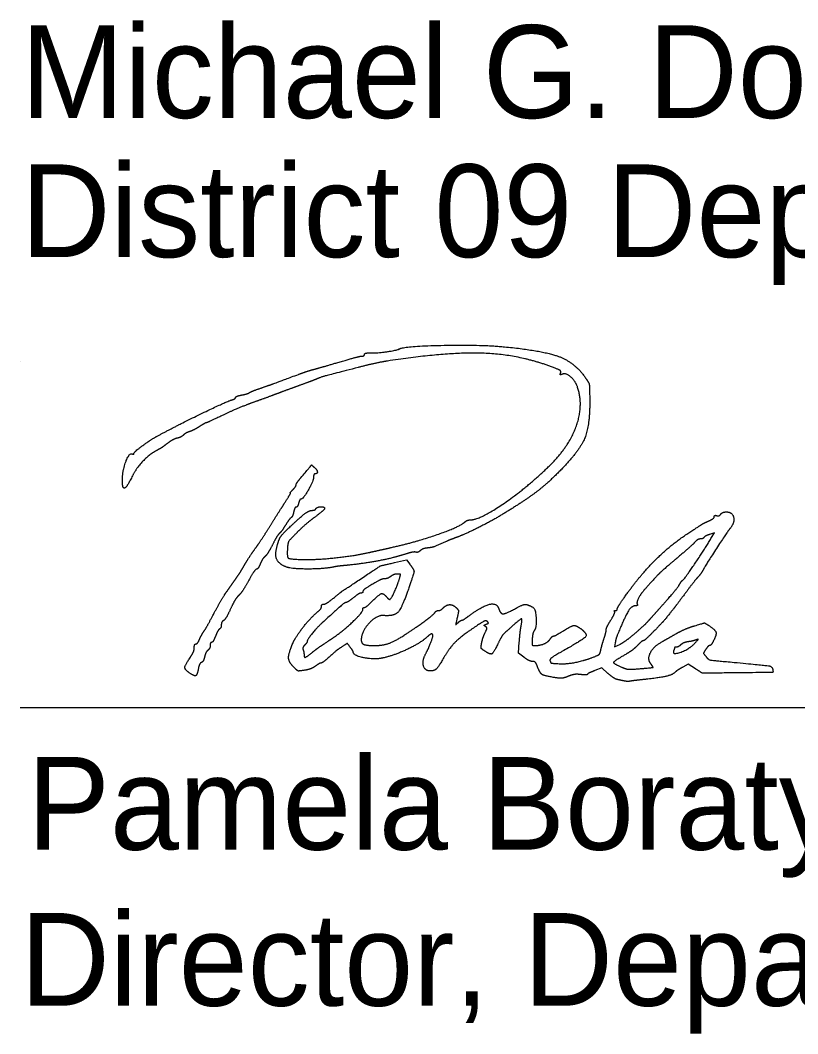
# Model space of a CAD drawing. Extents: x 0 to 34, y 0 to 22.
# Drawn here: x 24.528 to 25.701, y 7.305 to 8.834 of the extents above; entities that cross this region are included whole.
import ezdxf

# ---------------------------------------------------------------- set-up
doc = ezdxf.new("R2010")
doc.units = 0
for name, color, linetype in [('Default', 7, 'Continuous'), ('SH_Data', 7, 'Continuous'), ('SH_Text', 7, 'Continuous')]:
    doc.layers.add(name, color=color, linetype=linetype)

msp = doc.modelspace()

# ---------------------------------------------------------------- linework, layer by layer
at = {"layer": 'Default'}
for points in [[(25.5703, 8.0517), (25.5756, 8.0607), (25.5683, 8.0581)], [(25.0929, 8.0156), (25.1109, 8.0196), (25.1156, 8.0134)], [(25.2879, 7.8728), (25.2796, 7.8791), (25.281, 7.8962)], [(25.4259, 7.8947), (25.4249, 7.8883), (25.4335, 7.8927)], [(25.5467, 7.8554), (25.5361, 7.8622), (25.5277, 7.8577)], [(25.4148, 7.8484), (25.4057, 7.8567), (25.3951, 7.8526)]]:
    msp.add_lwpolyline(points, dxfattribs=at)
for points in [[(25.0563, 8.3319), (25.0659, 8.3317), (25.0969, 8.336), (25.1003, 8.3381)], [(25.1003, 8.3381), (25.1071, 8.3423), (25.2241, 8.3446), (25.2585, 8.3412)], [(25.2585, 8.3412), (25.3178, 8.3354), (25.3653, 8.3171), (25.3811, 8.2941)], [(25.0106, 8.3186), (25.0267, 8.3233), (25.0415, 8.3272), (25.0436, 8.3272)], [(25.0821, 8.3197), (25.0729, 8.3183), (25.0529, 8.3139), (25.0377, 8.31)], [(25.0436, 8.3272), (25.0457, 8.3272), (25.0473, 8.3283), (25.0473, 8.3297)], [(25.0473, 8.3297), (25.0473, 8.3311), (25.0514, 8.3321), (25.0563, 8.3319)], [(25.331, 8.3105), (25.2805, 8.3295), (25.1725, 8.3335), (25.0821, 8.3197)], [(24.9477, 8.2996), (24.9557, 8.3025), (24.9665, 8.3061), (24.9717, 8.3074)], [(24.9717, 8.3074), (24.977, 8.3088), (24.9945, 8.3138), (25.0106, 8.3186)], [(25.0377, 8.31), (24.9867, 8.2968), (24.9825, 8.2956), (24.9717, 8.2912)], [(25.3434, 8.3019), (25.3443, 8.3044), (25.3409, 8.3068), (25.331, 8.3105)], [(24.8913, 8.279), (24.9061, 8.2841), (24.9125, 8.2864), (24.9477, 8.2996)], [(24.9717, 8.2912), (24.9691, 8.2901), (24.9588, 8.2863), (24.9489, 8.2827)], [(25.3458, 8.2998), (25.3432, 8.2988), (25.3424, 8.2994), (25.3434, 8.3019)], [(25.3691, 8.2799), (25.3659, 8.2896), (25.3514, 8.302), (25.3458, 8.2998)], [(25.3811, 8.2941), (25.3861, 8.2868), (25.387, 8.2825), (25.3873, 8.2646)], [(24.8733, 8.2718), (24.8747, 8.2728), (24.8828, 8.276), (24.8913, 8.279)], [(24.9489, 8.2827), (24.939, 8.2791), (24.9239, 8.2736), (24.9153, 8.2703)], [(25.3236, 8.1587), (25.3546, 8.1881), (25.3784, 8.2516), (25.3691, 8.2799)], [(24.7353, 8.2068), (24.7656, 8.2231), (24.8392, 8.2587), (24.8475, 8.2612)], [(24.8475, 8.2612), (24.8505, 8.262), (24.8529, 8.2636), (24.8529, 8.2647)], [(24.8529, 8.2647), (24.8529, 8.2658), (24.857, 8.2674), (24.8619, 8.2684)], [(24.8619, 8.2684), (24.8669, 8.2693), (24.872, 8.2708), (24.8733, 8.2718)], [(24.9153, 8.2703), (24.9068, 8.2671), (24.8906, 8.2612), (24.8793, 8.2572)], [(25.3873, 8.2646), (25.3881, 8.2238), (25.372, 8.1841), (25.3426, 8.1542)], [(24.8793, 8.2572), (24.8681, 8.2532), (24.8478, 8.2447), (24.8341, 8.2382)], [(24.8341, 8.2382), (24.8205, 8.2317), (24.8088, 8.2264), (24.8083, 8.2264)], [(24.7835, 8.2132), (24.7802, 8.2122), (24.7761, 8.2099), (24.7743, 8.2081)], [(24.7983, 8.2208), (24.7934, 8.2177), (24.7867, 8.2143), (24.7835, 8.2132)], [(24.8083, 8.2264), (24.8077, 8.2264), (24.8032, 8.2239), (24.7983, 8.2208)], [(24.6993, 8.1802), (24.6993, 8.1823), (24.7247, 8.2011), (24.7353, 8.2068)], [(24.7646, 8.2033), (24.761, 8.2024), (24.7544, 8.1988), (24.7497, 8.1952)], [(24.7743, 8.2081), (24.7725, 8.2063), (24.7681, 8.2041), (24.7646, 8.2033)], [(24.7339, 8.1848), (24.7234, 8.1795), (24.7035, 8.1587), (24.6973, 8.1465)], [(24.7497, 8.1952), (24.7451, 8.1916), (24.738, 8.1869), (24.7339, 8.1848)], [(24.6822, 8.1423), (24.6823, 8.1555), (24.6929, 8.1821), (24.697, 8.1795)], [(24.697, 8.1795), (24.6983, 8.1788), (24.6993, 8.1791), (24.6993, 8.1802)], [(24.9495, 8.1413), (24.9681, 8.1634), (24.9674, 8.1628), (24.9715, 8.1594)], [(24.9715, 8.1594), (24.9758, 8.1559), (24.9767, 8.1496), (24.9729, 8.1496)], [(25.2069, 8.08), (25.221, 8.08), (25.2891, 8.1259), (25.3236, 8.1587)], [(25.3426, 8.1542), (25.324, 8.1354), (25.2916, 8.1104), (25.2611, 8.0916)], [(24.6835, 8.1286), (24.6827, 8.1294), (24.6821, 8.1356), (24.6822, 8.1423)], [(24.6973, 8.1465), (24.6907, 8.1336), (24.6854, 8.1268), (24.6835, 8.1286)], [(24.9441, 8.1326), (24.9441, 8.1338), (24.9466, 8.1377), (24.9495, 8.1413)], [(24.9705, 8.1445), (24.9705, 8.139), (24.9546, 8.1112), (24.9514, 8.1112)], [(24.9729, 8.1496), (24.9716, 8.1496), (24.9705, 8.1473), (24.9705, 8.1445)], [(24.9356, 8.1208), (24.935, 8.1208), (24.9367, 8.123), (24.9393, 8.1256)], [(24.9393, 8.1256), (24.942, 8.1283), (24.9441, 8.1314), (24.9441, 8.1326)], [(24.9266, 8.1051), (24.9321, 8.1138), (24.9362, 8.1208), (24.9356, 8.1208)], [(24.9514, 8.1112), (24.9503, 8.1112), (24.9488, 8.1085), (24.948, 8.1052)], [(24.9045, 8.0701), (24.9111, 8.0808), (24.9211, 8.0965), (24.9266, 8.1051)], [(24.9357, 8.0703), (24.9514, 8.0849), (24.9642, 8.0944), (24.9681, 8.0944)], [(24.9405, 8.092), (24.9397, 8.0881), (24.9379, 8.0842), (24.9367, 8.0834)], [(24.9443, 8.0992), (24.9431, 8.0992), (24.9414, 8.096), (24.9405, 8.092)], [(24.948, 8.1052), (24.9471, 8.1019), (24.9455, 8.0992), (24.9443, 8.0992)], [(24.9681, 8.0944), (24.9706, 8.0944), (24.9733, 8.0955), (24.9741, 8.0968)], [(24.9873, 8.0972), (24.9873, 8.0961), (24.9806, 8.0902), (24.9723, 8.0841)], [(24.9741, 8.0968), (24.9759, 8.0997), (24.9873, 8.1), (24.9873, 8.0972)], [(25.2611, 8.0916), (25.2419, 8.0798), (25.2006, 8.0588), (25.1865, 8.0537)], [(25.5851, 8.0886), (25.5866, 8.0905), (25.5903, 8.092), (25.5933, 8.092)], [(25.5933, 8.092), (25.6027, 8.092), (25.6064, 8.076), (25.599, 8.067)], [(24.9367, 8.0834), (24.9354, 8.0827), (24.9316, 8.0775), (24.9282, 8.072)], [(24.9723, 8.0841), (24.9641, 8.078), (24.9516, 8.0671), (24.9446, 8.0599)], [(25.0869, 8.0381), (25.1239, 8.0463), (25.1901, 8.0692), (25.1987, 8.0767)], [(25.1987, 8.0767), (25.2008, 8.0785), (25.2045, 8.08), (25.2069, 8.08)], [(25.5386, 8.0616), (25.5575, 8.0739), (25.5594, 8.075), (25.5675, 8.0787)], [(25.5675, 8.0787), (25.5718, 8.0806), (25.5753, 8.0834), (25.5753, 8.0849)], [(25.5753, 8.0849), (25.5753, 8.0865), (25.5769, 8.0871), (25.5788, 8.0864)], [(25.5788, 8.0864), (25.5806, 8.0857), (25.5835, 8.0867), (25.5851, 8.0886)], [(24.8828, 8.0372), (24.8882, 8.0447), (24.8979, 8.0595), (24.9045, 8.0701)], [(24.9144, 8.0356), (24.9172, 8.0487), (24.9233, 8.0587), (24.9357, 8.0703)], [(24.9282, 8.072), (24.9248, 8.0665), (24.9207, 8.0609), (24.919, 8.0596)], [(24.9446, 8.0599), (24.9338, 8.049), (24.9317, 8.0453), (24.9311, 8.0371)], [(25.4439, 7.9691), (25.4662, 7.9999), (25.5112, 8.0439), (25.5386, 8.0616)], [(25.599, 8.067), (25.5949, 8.062), (25.562, 8.0115), (25.5589, 8.0053)], [(24.919, 8.0596), (24.9173, 8.0582), (24.9127, 8.0506), (24.9087, 8.0426)], [(25.1709, 8.0475), (25.1538, 8.04), (25.149, 8.0383), (25.1423, 8.0376)], [(25.1865, 8.0537), (25.1819, 8.052), (25.1749, 8.0492), (25.1709, 8.0475)], [(25.5454, 8.0458), (25.5427, 8.0428), (25.5303, 8.0318), (25.5177, 8.0212)], [(25.5275, 7.9888), (25.5303, 7.9908), (25.5585, 8.0323), (25.5703, 8.0517)], [(25.5543, 8.0512), (25.5521, 8.0512), (25.5481, 8.0488), (25.5454, 8.0458)], [(25.5596, 8.0534), (25.5589, 8.0522), (25.5565, 8.0512), (25.5543, 8.0512)], [(25.5683, 8.0581), (25.5642, 8.0567), (25.5603, 8.0546), (25.5596, 8.0534)], [(24.8661, 8.0116), (24.8699, 8.0182), (24.8774, 8.0297), (24.8828, 8.0372)], [(24.9087, 8.0426), (24.9046, 8.0347), (24.8996, 8.0267), (24.8974, 8.0249)], [(24.9297, 8.0088), (24.9193, 8.0127), (24.9122, 8.0251), (24.9144, 8.0356)], [(24.9311, 8.0371), (24.9303, 8.0236), (24.9343, 8.0208), (24.9549, 8.0202)], [(24.9549, 8.0202), (24.9742, 8.0197), (25.032, 8.0258), (25.0533, 8.0306)], [(25.0533, 8.0306), (25.0613, 8.0324), (25.0764, 8.0357), (25.0869, 8.0381)], [(25.1247, 8.0313), (25.1231, 8.0319), (25.115, 8.0303), (25.1067, 8.0276)], [(25.1315, 8.0335), (25.1294, 8.0317), (25.1264, 8.0307), (25.1247, 8.0313)], [(25.1423, 8.0376), (25.1385, 8.0372), (25.1336, 8.0353), (25.1315, 8.0335)], [(24.8974, 8.0249), (24.8952, 8.0231), (24.892, 8.018), (24.8901, 8.0136)], [(25.1067, 8.0276), (25.0903, 8.0223), (25.0452, 8.0138), (25.0214, 8.0115)], [(25.0389, 7.9892), (25.0706, 8.0102), (25.072, 8.0109), (25.0929, 8.0156)], [(25.5177, 8.0212), (25.4981, 8.0047), (25.4864, 7.9933), (25.4697, 7.9744)], [(24.853, 7.991), (24.8564, 7.9957), (24.8622, 8.005), (24.8661, 8.0116)], [(24.8844, 8.0056), (24.8831, 8.0056), (24.8777, 7.9977), (24.8724, 7.9881)], [(24.8901, 8.0136), (24.8883, 8.0092), (24.8857, 8.0056), (24.8844, 8.0056)], [(25.001, 8.0089), (24.9873, 8.0059), (24.9378, 8.0058), (24.9297, 8.0088)], [(25.0214, 8.0115), (25.013, 8.0107), (25.0039, 8.0096), (25.001, 8.0089)], [(25.1156, 8.0134), (25.1222, 8.0047), (25.1221, 7.9998), (25.1143, 7.9773)], [(25.5589, 8.0053), (25.5571, 8.0019), (25.5532, 7.9964), (25.5502, 7.9932)], [(24.8395, 7.9718), (24.8436, 7.9776), (24.8497, 7.9862), (24.853, 7.991)], [(24.8724, 7.9881), (24.8671, 7.9784), (24.8604, 7.9684), (24.8575, 7.9659)], [(24.9997, 7.9612), (25.0134, 7.9723), (25.0115, 7.9709), (25.0389, 7.9892)], [(25.0686, 7.9881), (25.0542, 7.9801), (25.0449, 7.9738), (25.0449, 7.9718)], [(25.0784, 7.9912), (25.0761, 7.9912), (25.0717, 7.9898), (25.0686, 7.9881)], [(25.0871, 7.9947), (25.0845, 7.9928), (25.0806, 7.9912), (25.0784, 7.9912)], [(25.0856, 7.96), (25.0874, 7.96), (25.0971, 7.9811), (25.1003, 7.9918)], [(25.097, 7.9983), (25.0941, 7.9983), (25.0896, 7.9967), (25.0871, 7.9947)], [(25.1003, 7.9918), (25.102, 7.9976), (25.1016, 7.9984), (25.097, 7.9983)], [(25.4922, 7.9459), (25.5076, 7.963), (25.5211, 7.9793), (25.5235, 7.9837)], [(25.5235, 7.9837), (25.5247, 7.9858), (25.5265, 7.9882), (25.5275, 7.9888)], [(25.5502, 7.9932), (25.5473, 7.99), (25.5384, 7.9786), (25.5305, 7.968)], [(24.8206, 7.9396), (24.8269, 7.9515), (24.8354, 7.966), (24.8395, 7.9718)], [(25.0423, 7.9696), (25.0408, 7.9696), (25.0355, 7.9664), (25.0305, 7.9624)], [(25.0449, 7.9718), (25.0449, 7.9706), (25.0437, 7.9696), (25.0423, 7.9696)], [(25.0593, 7.9576), (25.0695, 7.9677), (25.076, 7.9696), (25.0809, 7.9636)], [(25.1143, 7.9773), (25.1041, 7.9474), (25.0921, 7.9343), (25.0761, 7.9356)], [(25.4289, 7.9458), (25.4289, 7.9472), (25.4357, 7.9577), (25.4439, 7.9691)], [(25.4697, 7.9744), (25.4639, 7.9678), (25.4576, 7.955), (25.4591, 7.9526)], [(25.5305, 7.968), (25.5226, 7.9573), (25.5149, 7.9471), (25.5134, 7.9453)], [(24.8575, 7.9659), (24.8547, 7.9633), (24.8492, 7.9542), (24.8452, 7.9456)], [(24.9825, 7.9494), (24.9825, 7.9513), (24.9841, 7.9528), (24.9859, 7.9528)], [(25.0194, 7.9552), (25.0175, 7.9552), (25.009, 7.9479), (24.9837, 7.9247)], [(24.9859, 7.9528), (24.9878, 7.9528), (24.994, 7.9566), (24.9997, 7.9612)], [(25.0305, 7.9624), (25.0255, 7.9585), (25.0205, 7.9552), (25.0194, 7.9552)], [(25.0473, 7.948), (25.0487, 7.948), (25.0541, 7.9523), (25.0593, 7.9576)], [(25.0809, 7.9636), (25.0826, 7.9616), (25.0847, 7.96), (25.0856, 7.96)], [(25.2041, 7.9345), (25.2244, 7.9497), (25.2471, 7.9553), (25.2501, 7.9459)], [(24.8051, 7.912), (24.8074, 7.9153), (24.8143, 7.9277), (24.8206, 7.9396)], [(24.8452, 7.9456), (24.8413, 7.937), (24.8366, 7.9291), (24.8347, 7.9281)], [(24.9391, 7.8933), (24.9435, 7.9038), (24.9668, 7.9332), (24.9771, 7.9416)], [(24.9771, 7.9416), (24.9801, 7.944), (24.9825, 7.9475), (24.9825, 7.9494)], [(24.9989, 7.9014), (25.0145, 7.9118), (25.0449, 7.9406), (25.0449, 7.9449)], [(25.0449, 7.9449), (25.0449, 7.9466), (25.046, 7.948), (25.0473, 7.948)], [(25.1109, 7.9083), (25.1295, 7.9207), (25.1519, 7.9374), (25.1537, 7.9401)], [(25.1537, 7.9401), (25.1547, 7.9418), (25.1571, 7.9432), (25.1589, 7.9432)], [(25.1589, 7.9432), (25.1607, 7.9432), (25.164, 7.945), (25.1661, 7.9471)], [(25.1661, 7.9471), (25.1711, 7.9521), (25.1811, 7.9521), (25.186, 7.9472)], [(25.186, 7.9472), (25.1892, 7.944), (25.1894, 7.9416), (25.1873, 7.9324)], [(25.2501, 7.9459), (25.2525, 7.9383), (25.2606, 7.9382), (25.2738, 7.9455)], [(25.2738, 7.9455), (25.2858, 7.9521), (25.293, 7.9528), (25.3013, 7.9482)], [(25.3013, 7.9482), (25.3056, 7.9458), (25.3073, 7.9178), (25.3034, 7.9126)], [(25.4192, 7.9289), (25.423, 7.9352), (25.4256, 7.941), (25.4248, 7.9418)], [(25.4248, 7.9418), (25.424, 7.9426), (25.4246, 7.9432), (25.4261, 7.9432)], [(25.4261, 7.9432), (25.4277, 7.9432), (25.4289, 7.9444), (25.4289, 7.9458)], [(25.4568, 7.9504), (25.4505, 7.9504), (25.4409, 7.9352), (25.4289, 7.906)], [(25.4591, 7.9526), (25.4598, 7.9514), (25.4588, 7.9504), (25.4568, 7.9504)], [(25.4766, 7.9284), (25.4798, 7.9319), (25.4868, 7.9398), (25.4922, 7.9459)], [(25.5134, 7.9453), (25.5002, 7.9289), (25.4956, 7.9237), (25.4837, 7.9116)], [(24.8347, 7.9281), (24.8329, 7.927), (24.8313, 7.9241), (24.8313, 7.9216)], [(24.9837, 7.9247), (24.9746, 7.9163), (24.9609, 7.8992), (24.9609, 7.8963)], [(25.0761, 7.9356), (25.0657, 7.9365), (25.0425, 7.9112), (25.0425, 7.8989)], [(25.1873, 7.9324), (25.1849, 7.9222), (25.185, 7.9217), (25.1888, 7.9251)], [(25.1888, 7.9251), (25.1911, 7.9272), (25.1937, 7.9288), (25.1947, 7.9288)], [(25.1947, 7.9288), (25.1957, 7.9288), (25.1999, 7.9314), (25.2041, 7.9345)], [(25.2328, 7.9267), (25.231, 7.9285), (25.2251, 7.9258), (25.2126, 7.9173)], [(25.2299, 7.9191), (25.2277, 7.9205), (25.228, 7.9214), (25.2311, 7.9226)], [(25.2311, 7.9226), (25.2341, 7.9237), (25.2346, 7.9249), (25.2328, 7.9267)], [(25.2739, 7.9227), (25.258, 7.9086), (25.2542, 7.9042), (25.2487, 7.8929)], [(25.284, 7.921), (25.2858, 7.9305), (25.2832, 7.9309), (25.2739, 7.9227)], [(25.4122, 7.9141), (25.4121, 7.916), (25.4153, 7.9226), (25.4192, 7.9289)], [(25.4565, 7.9095), (25.4645, 7.9164), (25.4735, 7.9248), (25.4766, 7.9284)], [(25.5458, 7.9202), (25.5599, 7.9245), (25.5611, 7.9245), (25.5669, 7.9206)], [(24.7983, 7.8994), (24.7998, 7.903), (24.8029, 7.9087), (24.8051, 7.912)], [(24.8288, 7.9155), (24.8275, 7.9147), (24.8246, 7.9098), (24.8226, 7.9046)], [(24.8313, 7.9216), (24.8313, 7.9191), (24.8302, 7.9164), (24.8288, 7.9155)], [(25.0625, 7.8904), (25.0755, 7.8904), (25.0946, 7.8975), (25.1109, 7.9083)], [(25.1505, 7.9051), (25.1505, 7.9082), (25.1466, 7.9077), (25.1429, 7.9042)], [(25.2126, 7.9173), (25.1928, 7.9038), (25.1756, 7.8868), (25.1673, 7.8724)], [(25.2241, 7.8936), (25.2249, 7.8978), (25.2272, 7.9048), (25.2292, 7.9092)], [(25.2292, 7.9092), (25.2321, 7.9155), (25.2323, 7.9177), (25.2299, 7.9191)], [(25.281, 7.8962), (25.2818, 7.9055), (25.2831, 7.9167), (25.284, 7.921)], [(25.3034, 7.9126), (25.3022, 7.911), (25.3009, 7.9053), (25.3005, 7.9)], [(25.333, 7.9048), (25.3342, 7.9048), (25.3403, 7.9081), (25.3465, 7.912)], [(25.3748, 7.915), (25.3844, 7.9074), (25.3776, 7.8995), (25.346, 7.8817)], [(25.3465, 7.912), (25.3595, 7.9202), (25.3671, 7.921), (25.3748, 7.915)], [(25.4086, 7.9), (25.4106, 7.906), (25.4122, 7.9123), (25.4122, 7.9141)], [(25.4335, 7.8927), (25.4383, 7.8952), (25.4486, 7.9027), (25.4565, 7.9095)], [(25.4837, 7.9116), (25.4762, 7.9039), (25.4692, 7.8976), (25.4681, 7.8976)], [(25.497, 7.8965), (25.4998, 7.8981), (25.5086, 7.903), (25.5165, 7.9076)], [(25.5165, 7.9076), (25.5245, 7.9121), (25.5376, 7.9178), (25.5458, 7.9202)], [(25.5669, 7.9206), (25.5766, 7.9143), (25.579, 7.9069), (25.5743, 7.8979)], [(24.7905, 7.8871), (24.7905, 7.8903), (24.7916, 7.8928), (24.793, 7.8928)], [(24.793, 7.8928), (24.7943, 7.8928), (24.7967, 7.8958), (24.7983, 7.8994)], [(24.8167, 7.8952), (24.8155, 7.8952), (24.8145, 7.8932), (24.8145, 7.8907)], [(24.8226, 7.9046), (24.8205, 7.8994), (24.8179, 7.8952), (24.8167, 7.8952)], [(24.9407, 7.8576), (24.9331, 7.8652), (24.9325, 7.8781), (24.9391, 7.8933)], [(24.9609, 7.8963), (24.9609, 7.8955), (24.9593, 7.8932), (24.9572, 7.8911)], [(24.9674, 7.8791), (24.9749, 7.8852), (24.9801, 7.8889), (24.9989, 7.9014)], [(25.0259, 7.8879), (25.0215, 7.8937), (25.0214, 7.8937), (25.0147, 7.8892)], [(25.0425, 7.8989), (25.0425, 7.8937), (25.0504, 7.8904), (25.0625, 7.8904)], [(25.1429, 7.9042), (25.1333, 7.895), (25.0946, 7.8762), (25.0761, 7.8718)], [(25.14, 7.8784), (25.1441, 7.8861), (25.1505, 7.9024), (25.1505, 7.9051)], [(25.2288, 7.8821), (25.2238, 7.8854), (25.223, 7.8873), (25.2241, 7.8936)], [(25.2487, 7.8929), (25.2421, 7.8792), (25.2372, 7.8765), (25.2288, 7.8821)], [(25.3005, 7.9), (25.3, 7.8924), (25.3007, 7.8904), (25.3038, 7.8904)], [(25.3038, 7.8904), (25.3121, 7.8904), (25.3241, 7.8953), (25.3274, 7.8999)], [(25.3274, 7.8999), (25.3293, 7.9026), (25.3318, 7.9048), (25.333, 7.9048)], [(25.4039, 7.883), (25.4046, 7.8864), (25.4067, 7.8941), (25.4086, 7.9)], [(25.4289, 7.906), (25.4278, 7.9034), (25.4264, 7.8983), (25.4259, 7.8947)], [(25.4681, 7.8976), (25.467, 7.8976), (25.4632, 7.8945), (25.4596, 7.8907)], [(25.4799, 7.8622), (25.4739, 7.8696), (25.4837, 7.8893), (25.497, 7.8965)], [(25.5139, 7.8823), (25.5114, 7.8757), (25.5369, 7.8847), (25.5453, 7.8933)], [(25.5249, 7.8916), (25.5228, 7.8896), (25.5197, 7.888), (25.5182, 7.888)], [(25.5359, 7.8961), (25.5321, 7.8956), (25.5271, 7.8936), (25.5249, 7.8916)], [(25.5477, 7.8989), (25.5451, 7.8979), (25.5398, 7.8966), (25.5359, 7.8961)], [(25.5453, 7.8933), (25.5508, 7.8989), (25.5514, 7.9002), (25.5477, 7.8989)], [(25.5743, 7.8979), (25.5722, 7.8938), (25.5695, 7.8904), (25.5684, 7.8904)], [(24.7847, 7.8729), (24.7879, 7.8776), (24.7905, 7.884), (24.7905, 7.8871)], [(24.8111, 7.8833), (24.8092, 7.8818), (24.8069, 7.8772), (24.8061, 7.8733)], [(24.8145, 7.8907), (24.8145, 7.8882), (24.813, 7.8849), (24.8111, 7.8833)], [(24.9572, 7.8911), (24.9551, 7.8891), (24.9541, 7.8858), (24.9548, 7.8839)], [(24.9548, 7.8839), (24.9555, 7.882), (24.9561, 7.8789), (24.9561, 7.877)], [(24.9561, 7.877), (24.9561, 7.8722), (24.9596, 7.8728), (24.9674, 7.8791)], [(25.0147, 7.8892), (25.0064, 7.8839), (25.0039, 7.8818), (24.9927, 7.8718)], [(25.0305, 7.8805), (25.0305, 7.8813), (25.0284, 7.8846), (25.0259, 7.8879)], [(25.0761, 7.8718), (25.0633, 7.8687), (25.0307, 7.8749), (25.0305, 7.8805)], [(25.1467, 7.852), (25.1383, 7.852), (25.1343, 7.8678), (25.14, 7.8784)], [(25.346, 7.8817), (25.3328, 7.8743), (25.3266, 7.8695), (25.3274, 7.8673)], [(25.3912, 7.8723), (25.4, 7.8757), (25.4029, 7.8781), (25.4039, 7.883)], [(25.4416, 7.8771), (25.4236, 7.8666), (25.4226, 7.8634), (25.4355, 7.8578)], [(25.4596, 7.8907), (25.4559, 7.8868), (25.4479, 7.8807), (25.4416, 7.8771)], [(25.5153, 7.887), (25.5153, 7.8865), (25.5147, 7.8843), (25.5139, 7.8823)], [(25.5182, 7.888), (25.5166, 7.888), (25.5153, 7.8876), (25.5153, 7.887)], [(25.5625, 7.8846), (25.559, 7.8792), (25.559, 7.8784), (25.5628, 7.8737)], [(25.5684, 7.8904), (25.5672, 7.8904), (25.5646, 7.8878), (25.5625, 7.8846)], [(24.783, 7.8492), (24.776, 7.8541), (24.7765, 7.8608), (24.7847, 7.8729)], [(24.8014, 7.8649), (24.7996, 7.8642), (24.7975, 7.8601), (24.7967, 7.8557)], [(24.8061, 7.8733), (24.8052, 7.8693), (24.8031, 7.8655), (24.8014, 7.8649)], [(24.9819, 7.864), (24.9808, 7.864), (24.977, 7.8619), (24.9734, 7.8593)], [(24.9927, 7.8718), (24.9879, 7.8675), (24.983, 7.864), (24.9819, 7.864)], [(25.1673, 7.8724), (25.1592, 7.8583), (25.1528, 7.852), (25.1467, 7.852)], [(25.3009, 7.8664), (25.2983, 7.8664), (25.2925, 7.8693), (25.2879, 7.8728)], [(25.3084, 7.8586), (25.3065, 7.8638), (25.304, 7.8664), (25.3009, 7.8664)], [(25.3274, 7.8673), (25.3287, 7.8639), (25.3294, 7.8637), (25.3413, 7.863)], [(25.3413, 7.863), (25.3519, 7.8624), (25.378, 7.8673), (25.3912, 7.8723)], [(25.4623, 7.8554), (25.4819, 7.857), (25.4836, 7.8576), (25.4799, 7.8622)], [(25.5628, 7.8737), (25.5665, 7.8691), (25.5715, 7.8681), (25.6054, 7.865)], [(25.6054, 7.865), (25.6544, 7.8604), (25.6627, 7.8589), (25.6636, 7.8541)], [(24.7967, 7.8557), (24.7949, 7.8459), (24.7907, 7.8439), (24.783, 7.8492)], [(24.9569, 7.853), (24.9482, 7.8517), (24.9461, 7.8523), (24.9407, 7.8576)], [(24.9734, 7.8593), (24.9699, 7.8567), (24.9624, 7.8539), (24.9569, 7.853)], [(25.3338, 7.8421), (25.3187, 7.8445), (25.3119, 7.849), (25.3084, 7.8586)], [(25.3737, 7.8466), (25.368, 7.8473), (25.3607, 7.8463), (25.3549, 7.844)], [(25.3838, 7.8469), (25.3834, 7.846), (25.3789, 7.8459), (25.3737, 7.8466)], [(25.3951, 7.8526), (25.3893, 7.8504), (25.3842, 7.8478), (25.3838, 7.8469)], [(25.4295, 7.839), (25.4265, 7.8396), (25.4199, 7.8439), (25.4148, 7.8484)], [(25.4355, 7.8578), (25.4424, 7.8549), (25.4488, 7.8543), (25.4623, 7.8554)], [(25.516, 7.8499), (25.5122, 7.8461), (25.4908, 7.8413), (25.4673, 7.8389)], [(25.5277, 7.8577), (25.5231, 7.8552), (25.5178, 7.8517), (25.516, 7.8499)], [(25.5933, 7.849), (25.5576, 7.8486), (25.5573, 7.8487), (25.5467, 7.8554)], [(25.6636, 7.8541), (25.6644, 7.8499), (25.6625, 7.8497), (25.5933, 7.849)], [(25.3549, 7.844), (25.3479, 7.8412), (25.3423, 7.8407), (25.3338, 7.8421)], [(25.4397, 7.8368), (25.4371, 7.8374), (25.4325, 7.8383), (25.4295, 7.839)], [(25.4481, 7.8365), (25.4462, 7.8361), (25.4424, 7.8363), (25.4397, 7.8368)], [(25.4673, 7.8389), (25.4588, 7.838), (25.4501, 7.8369), (25.4481, 7.8365)]]:
    msp.add_open_spline(points, degree=2, dxfattribs=at)
at = {"layer": 'SH_Data'}
for p, q in [((24.5279, 8.3191), (24.5279, 8.3191)), ((24.5279, 8.3191), (24.5279, 8.3191)), ((24.5279, 8.3191), (24.5279, 8.3191)), ((24.5279, 7.7968), (28.0279, 7.7968)), ((24.5279, 7.7968), (28.0279, 7.7968))]:
    msp.add_line(p, q, dxfattribs=at)

# ---------------------------------------------------------------- texts
at = {"layer": 'SH_Text'}
for s, p in [('Michael G. Dombrowski', (24.5289, 8.6865)), ('District 09 Deputy Director', (24.5289, 8.4765)), ('Pamela Boratyn', (24.5384, 7.5823)), ('Director, Department of Transportation', (24.5279, 7.3468))]:
    msp.add_text(s, height=0.14, dxfattribs=at).set_placement(p)

doc.saveas('drawing.dxf')
